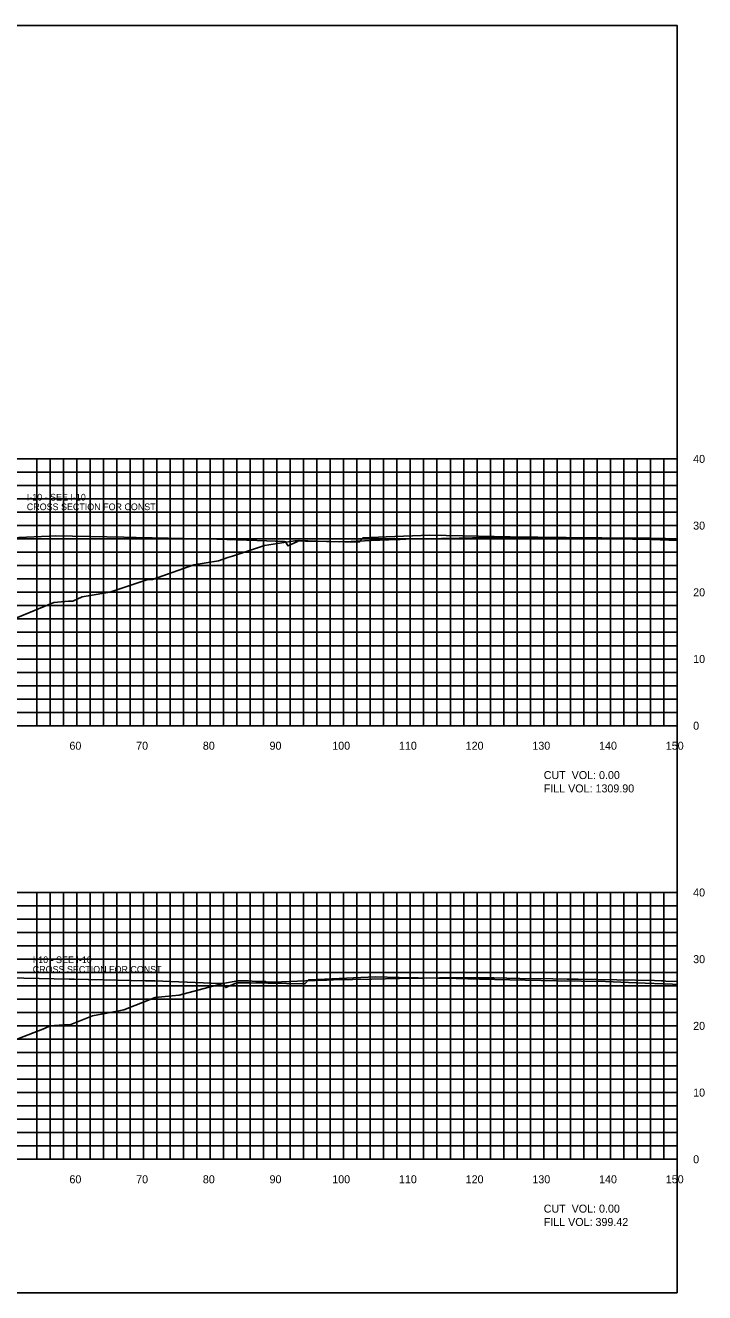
# Model space of a CAD drawing. Extents: x 1797518 to 1804843, y 248068 to 251132.
# Drawn here: x 1803023.3 to 1803125.1, y 250079.4 to 250269.4 of the extents above; entities that cross this region are included whole.
import ezdxf

# ---------------------------------------------------------------- set-up
doc = ezdxf.new("R2010")
doc.units = 0
for name, color, linetype in [('10', 7, 'Continuous'), ('3', 7, 'Continuous'), ('31', 7, 'Continuous'), ('60', 7, 'Continuous'), ('ANNO-TXT', 7, 'Continuous'), ('CL-CNST', 7, 'Continuous'), ('Level 62', 7, 'Continuous'), ('M-ROADS', 7, 'Continuous')]:
    doc.layers.add(name, color=color, linetype=linetype)

msp = doc.modelspace()

# ---------------------------------------------------------------- linework, layer by layer
msp.add_lwpolyline([(1802821, 250079.43), (1803121, 250079.43), (1803121, 250269.43), (1802821, 250269.43)], close=True)
at = {"layer": '60'}
for p, q in [((1803121, 250164.43), (1803121, 250204.43)), ((1803121.06, 250204.43), (1803121, 250204.43)), ((1803121.06, 250194.43), (1803121, 250194.43)), ((1803121.06, 250184.43), (1803121, 250184.43)), ((1803121.06, 250174.43), (1803121, 250174.43)), ((1802821, 250164.43), (1803121, 250164.43)), ((1803031, 250164.37), (1803031, 250164.43)), ((1803041, 250164.37), (1803041, 250164.43)), ((1803051, 250164.37), (1803051, 250164.43)), ((1803061, 250164.37), (1803061, 250164.43)), ((1803071, 250164.37), (1803071, 250164.43)), ((1803081, 250164.37), (1803081, 250164.43)), ((1803091, 250164.37), (1803091, 250164.43)), ((1803101, 250164.37), (1803101, 250164.43)), ((1803111, 250164.37), (1803111, 250164.43)), ((1803121, 250164.37), (1803121, 250164.43)), ((1803121.06, 250164.43), (1803121, 250164.43)), ((1803121, 250099.43), (1803121, 250139.43)), ((1803121.06, 250139.43), (1803121, 250139.43)), ((1803121.06, 250129.43), (1803121, 250129.43)), ((1803121.06, 250119.43), (1803121, 250119.43)), ((1803121.06, 250109.43), (1803121, 250109.43)), ((1802821, 250099.43), (1803121, 250099.43)), ((1803031, 250099.37), (1803031, 250099.43)), ((1803041, 250099.37), (1803041, 250099.43)), ((1803051, 250099.37), (1803051, 250099.43)), ((1803061, 250099.37), (1803061, 250099.43)), ((1803071, 250099.37), (1803071, 250099.43)), ((1803081, 250099.37), (1803081, 250099.43)), ((1803091, 250099.37), (1803091, 250099.43)), ((1803101, 250099.37), (1803101, 250099.43)), ((1803111, 250099.37), (1803111, 250099.43)), ((1803121, 250099.37), (1803121, 250099.43)), ((1803121.06, 250099.43), (1803121, 250099.43))]:
    msp.add_line(p, q, dxfattribs=at)
at = {"layer": 'CL-CNST'}
for points in [[(1803017.74, 250192.46), (1803026.84, 250192.84), (1803027.82, 250192.88), (1803038.07, 250192.68), (1803039.91, 250192.64), (1803049.48, 250192.46), (1803052.01, 250192.41), (1803059.48, 250192.13), (1803062.09, 250192.03), (1803062.24, 250192.02), (1803062.3, 250192.02), (1803062.54, 250191.58), (1803062.63, 250191.42), (1803063.87, 250191.97), (1803064.35, 250192.18), (1803066.93, 250192.12), (1803073.31, 250191.97), (1803073.49, 250192.17), (1803073.86, 250192.58), (1803077.36, 250192.73), (1803083.92, 250193.01), (1803088.82, 250192.91), (1803095.99, 250192.77), (1803100.14, 250192.69), (1803105.16, 250192.59), (1803111.42, 250192.47), (1803117.22, 250192.36), (1803121, 250192.21)], [(1803018.54, 250126.66), (1803029.85, 250126.43), (1803030.62, 250126.42), (1803041.29, 250126.2), (1803042.71, 250126.17), (1803051.14, 250125.85), (1803052.77, 250125.79), (1803052.95, 250125.78), (1803052.99, 250125.78), (1803053.26, 250125.28), (1803053.32, 250125.18), (1803054.73, 250125.77), (1803055.04, 250125.9), (1803056.91, 250125.86), (1803065.19, 250125.73), (1803065.32, 250125.87), (1803065.74, 250126.34), (1803068.16, 250126.44), (1803075.79, 250126.76), (1803079.33, 250126.68), (1803087.85, 250126.51), (1803091.39, 250126.44), (1803098.21, 250126.3), (1803103.08, 250126.2), (1803110.25, 250126.06), (1803114.86, 250125.88), (1803120.29, 250125.68), (1803121, 250125.65)]]:
    msp.add_lwpolyline(points, dxfattribs=at)
at = {"layer": 'Level 62'}
for p, q in [((1802821, 250204.43), (1803121, 250204.43)), ((1803025, 250164.43), (1803025, 250204.43)), ((1803027, 250164.43), (1803027, 250204.43)), ((1803029, 250164.43), (1803029, 250204.43)), ((1803031, 250164.43), (1803031, 250204.43)), ((1803033, 250164.43), (1803033, 250204.43)), ((1803035, 250164.43), (1803035, 250204.43)), ((1803037, 250164.43), (1803037, 250204.43)), ((1803039, 250164.43), (1803039, 250204.43)), ((1803041, 250164.43), (1803041, 250204.43)), ((1803043, 250164.43), (1803043, 250204.43)), ((1803045, 250164.43), (1803045, 250204.43)), ((1803047, 250164.43), (1803047, 250204.43)), ((1803049, 250164.43), (1803049, 250204.43)), ((1803051, 250164.43), (1803051, 250204.43)), ((1803053, 250164.43), (1803053, 250204.43)), ((1803055, 250164.43), (1803055, 250204.43)), ((1803057, 250164.43), (1803057, 250204.43)), ((1803059, 250164.43), (1803059, 250204.43)), ((1803061, 250164.43), (1803061, 250204.43)), ((1803063, 250164.43), (1803063, 250204.43)), ((1803065, 250164.43), (1803065, 250204.43)), ((1803067, 250164.43), (1803067, 250204.43)), ((1803069, 250164.43), (1803069, 250204.43)), ((1803071, 250164.43), (1803071, 250204.43)), ((1803073, 250164.43), (1803073, 250204.43)), ((1803075, 250164.43), (1803075, 250204.43)), ((1803077, 250164.43), (1803077, 250204.43)), ((1803079, 250164.43), (1803079, 250204.43)), ((1803081, 250164.43), (1803081, 250204.43)), ((1803083, 250164.43), (1803083, 250204.43)), ((1803085, 250164.43), (1803085, 250204.43)), ((1803087, 250164.43), (1803087, 250204.43)), ((1803089, 250164.43), (1803089, 250204.43)), ((1803091, 250164.43), (1803091, 250204.43)), ((1803093, 250164.43), (1803093, 250204.43)), ((1803095, 250164.43), (1803095, 250204.43)), ((1803097, 250164.43), (1803097, 250204.43)), ((1803099, 250164.43), (1803099, 250204.43)), ((1803101, 250164.43), (1803101, 250204.43)), ((1803103, 250164.43), (1803103, 250204.43)), ((1803105, 250164.43), (1803105, 250204.43)), ((1803107, 250164.43), (1803107, 250204.43)), ((1803109, 250164.43), (1803109, 250204.43)), ((1803111, 250164.43), (1803111, 250204.43)), ((1803113, 250164.43), (1803113, 250204.43)), ((1803115, 250164.43), (1803115, 250204.43)), ((1803117, 250164.43), (1803117, 250204.43)), ((1803119, 250164.43), (1803119, 250204.43)), ((1803121, 250164.43), (1803121, 250204.43)), ((1802821, 250202.43), (1803121, 250202.43)), ((1802821, 250200.43), (1803121, 250200.43)), ((1802821, 250198.43), (1803121, 250198.43)), ((1802821, 250196.43), (1803121, 250196.43)), ((1802821, 250194.43), (1803121, 250194.43)), ((1802821, 250192.43), (1803121, 250192.43)), ((1802821, 250190.43), (1803121, 250190.43)), ((1802821, 250188.43), (1803121, 250188.43)), ((1802821, 250186.43), (1803121, 250186.43)), ((1802821, 250184.43), (1803121, 250184.43)), ((1802821, 250182.43), (1803121, 250182.43)), ((1802821, 250180.43), (1803121, 250180.43)), ((1802821, 250178.43), (1803121, 250178.43)), ((1802821, 250176.43), (1803121, 250176.43)), ((1802821, 250174.43), (1803121, 250174.43)), ((1802821, 250172.43), (1803121, 250172.43)), ((1802821, 250170.43), (1803121, 250170.43)), ((1802821, 250168.43), (1803121, 250168.43)), ((1802821, 250166.43), (1803121, 250166.43)), ((1802821, 250164.43), (1803121, 250164.43)), ((1802821, 250139.43), (1803121, 250139.43)), ((1803025, 250099.43), (1803025, 250139.43)), ((1803027, 250099.43), (1803027, 250139.43)), ((1803029, 250099.43), (1803029, 250139.43)), ((1803031, 250099.43), (1803031, 250139.43)), ((1803033, 250099.43), (1803033, 250139.43)), ((1803035, 250099.43), (1803035, 250139.43)), ((1803037, 250099.43), (1803037, 250139.43)), ((1803039, 250099.43), (1803039, 250139.43)), ((1803041, 250099.43), (1803041, 250139.43)), ((1803043, 250099.43), (1803043, 250139.43)), ((1803045, 250099.43), (1803045, 250139.43)), ((1803047, 250099.43), (1803047, 250139.43)), ((1803049, 250099.43), (1803049, 250139.43)), ((1803051, 250099.43), (1803051, 250139.43)), ((1803053, 250099.43), (1803053, 250139.43)), ((1803055, 250099.43), (1803055, 250139.43)), ((1803057, 250099.43), (1803057, 250139.43)), ((1803059, 250099.43), (1803059, 250139.43)), ((1803061, 250099.43), (1803061, 250139.43)), ((1803063, 250099.43), (1803063, 250139.43)), ((1803065, 250099.43), (1803065, 250139.43)), ((1803067, 250099.43), (1803067, 250139.43)), ((1803069, 250099.43), (1803069, 250139.43)), ((1803071, 250099.43), (1803071, 250139.43)), ((1803073, 250099.43), (1803073, 250139.43)), ((1803075, 250099.43), (1803075, 250139.43)), ((1803077, 250099.43), (1803077, 250139.43)), ((1803079, 250099.43), (1803079, 250139.43)), ((1803081, 250099.43), (1803081, 250139.43)), ((1803083, 250099.43), (1803083, 250139.43)), ((1803085, 250099.43), (1803085, 250139.43)), ((1803087, 250099.43), (1803087, 250139.43)), ((1803089, 250099.43), (1803089, 250139.43)), ((1803091, 250099.43), (1803091, 250139.43)), ((1803093, 250099.43), (1803093, 250139.43)), ((1803095, 250099.43), (1803095, 250139.43)), ((1803097, 250099.43), (1803097, 250139.43)), ((1803099, 250099.43), (1803099, 250139.43)), ((1803101, 250099.43), (1803101, 250139.43)), ((1803103, 250099.43), (1803103, 250139.43)), ((1803105, 250099.43), (1803105, 250139.43)), ((1803107, 250099.43), (1803107, 250139.43)), ((1803109, 250099.43), (1803109, 250139.43)), ((1803111, 250099.43), (1803111, 250139.43)), ((1803113, 250099.43), (1803113, 250139.43)), ((1803115, 250099.43), (1803115, 250139.43)), ((1803117, 250099.43), (1803117, 250139.43)), ((1803119, 250099.43), (1803119, 250139.43)), ((1803121, 250099.43), (1803121, 250139.43)), ((1802821, 250137.43), (1803121, 250137.43)), ((1802821, 250135.43), (1803121, 250135.43)), ((1802821, 250133.43), (1803121, 250133.43)), ((1802821, 250131.43), (1803121, 250131.43)), ((1802821, 250129.43), (1803121, 250129.43)), ((1802821, 250127.43), (1803121, 250127.43)), ((1802821, 250125.43), (1803121, 250125.43)), ((1802821, 250123.43), (1803121, 250123.43)), ((1802821, 250121.43), (1803121, 250121.43)), ((1802821, 250119.43), (1803121, 250119.43)), ((1802821, 250117.43), (1803121, 250117.43)), ((1802821, 250115.43), (1803121, 250115.43)), ((1802821, 250113.43), (1803121, 250113.43)), ((1802821, 250111.43), (1803121, 250111.43)), ((1802821, 250109.43), (1803121, 250109.43)), ((1802821, 250107.43), (1803121, 250107.43)), ((1802821, 250105.43), (1803121, 250105.43)), ((1802821, 250103.43), (1803121, 250103.43)), ((1802821, 250101.43), (1803121, 250101.43)), ((1802821, 250099.43), (1803121, 250099.43))]:
    msp.add_line(p, q, dxfattribs=at)
at = {"layer": 'M-ROADS'}
for points in [[(1803020.65, 250180.05), (1803027.58, 250182.91), (1803029.78, 250183.08), (1803030.43, 250183.12), (1803031.81, 250183.75), (1803032.72, 250183.9), (1803035.94, 250184.44), (1803041.48, 250186.32), (1803042.33, 250186.34), (1803048.54, 250188.56), (1803052.24, 250189.17), (1803053.64, 250189.63), (1803054.34, 250189.83), (1803059.13, 250191.45), (1803063.71, 250192.14), (1803064.57, 250192.13), (1803064.81, 250192.13), (1803065.27, 250192.12), (1803066.55, 250192.09), (1803070.32, 250192.01), (1803072.15, 250192.07), (1803075.15, 250192.19), (1803079.09, 250192.34), (1803079.47, 250192.36), (1803080.35, 250192.39), (1803088.33, 250192.54), (1803092.25, 250192.63), (1803099.76, 250192.66), (1803104.34, 250192.66), (1803109.69, 250192.61), (1803116.95, 250192.53), (1803119.25, 250192.49), (1803121, 250192.46)], [(1803018.11, 250115.94), (1803026.14, 250119.03), (1803027.03, 250119.45), (1803028.99, 250119.58), (1803030.11, 250119.65), (1803033.37, 250120.93), (1803035.49, 250121.34), (1803038.06, 250121.83), (1803042.77, 250123.66), (1803044.23, 250123.82), (1803046.36, 250124.04), (1803052.9, 250125.79), (1803055.14, 250126.18), (1803056.75, 250126.18), (1803057.85, 250126.07), (1803059.27, 250126.07), (1803059.46, 250125.96), (1803061.68, 250126.04), (1803065.31, 250126.19), (1803068.23, 250126.29), (1803068.51, 250126.3), (1803069.49, 250126.32), (1803075.17, 250126.44), (1803081.48, 250126.59), (1803083.03, 250126.6), (1803085.36, 250126.61), (1803090.23, 250126.62), (1803093.5, 250126.61), (1803097.4, 250126.54), (1803102.38, 250126.47), (1803104.5, 250126.44), (1803106.15, 250126.42), (1803111.95, 250126.31), (1803117.63, 250126.21), (1803118.66, 250126.17), (1803118.89, 250126.17), (1803119.31, 250126.15), (1803121, 250126.07)]]:
    msp.add_lwpolyline(points, dxfattribs=at)

# ---------------------------------------------------------------- texts
at = {"layer": '10'}
for s, p in [('60', (1803029.9, 250160.83)), ('70', (1803039.9, 250160.83)), ('80', (1803049.9, 250160.83)), ('90', (1803059.9, 250160.83)), ('100', (1803069.3, 250160.83)), ('110', (1803079.3, 250160.83)), ('120', (1803089.3, 250160.83)), ('130', (1803099.3, 250160.83)), ('140', (1803109.3, 250160.83)), ('150', (1803119.3, 250160.83)), ('60', (1803029.9, 250095.83)), ('70', (1803039.9, 250095.83)), ('80', (1803049.9, 250095.83)), ('90', (1803059.9, 250095.83)), ('100', (1803069.3, 250095.83)), ('110', (1803079.3, 250095.83)), ('120', (1803089.3, 250095.83)), ('130', (1803099.3, 250095.83)), ('140', (1803109.3, 250095.83)), ('150', (1803119.3, 250095.83))]:
    msp.add_text(s, height=1.2, dxfattribs=at).set_placement(p)
at = {"layer": '3'}
for s, p in [('CROSS SECTION FOR CONST ', (1803023.51, 250196.75)), ('I-10 - SEE I-10', (1803023.51, 250198.19)), ('I-10 - SEE I-10', (1803024.4, 250128.84)), ('CROSS SECTION FOR CONST ', (1803024.4, 250127.4))]:
    msp.add_text(s, height=1, dxfattribs=at).set_placement(p)
at = {"layer": '31'}
for s, p in [('40', (1803123.4, 250203.83)), ('30', (1803123.4, 250193.83)), ('20', (1803123.4, 250183.83)), ('10', (1803123.4, 250173.83)), ('0', (1803123.4, 250163.83)), ('40', (1803123.4, 250138.83)), ('30', (1803123.4, 250128.83)), ('20', (1803123.4, 250118.83)), ('10', (1803123.4, 250108.83)), ('0', (1803123.4, 250098.83))]:
    msp.add_text(s, height=1.2, dxfattribs=at).set_placement(p)
at = {"layer": 'ANNO-TXT'}
for s, p in [('CUT  VOL: 0.00', (1803101, 250156.43)), ('FILL VOL: 1309.90', (1803101, 250154.43)), ('CUT  VOL: 0.00', (1803101, 250091.43)), ('FILL VOL: 399.42', (1803101, 250089.43))]:
    msp.add_text(s, height=1.2, dxfattribs=at).set_placement(p)

doc.saveas('drawing.dxf')
